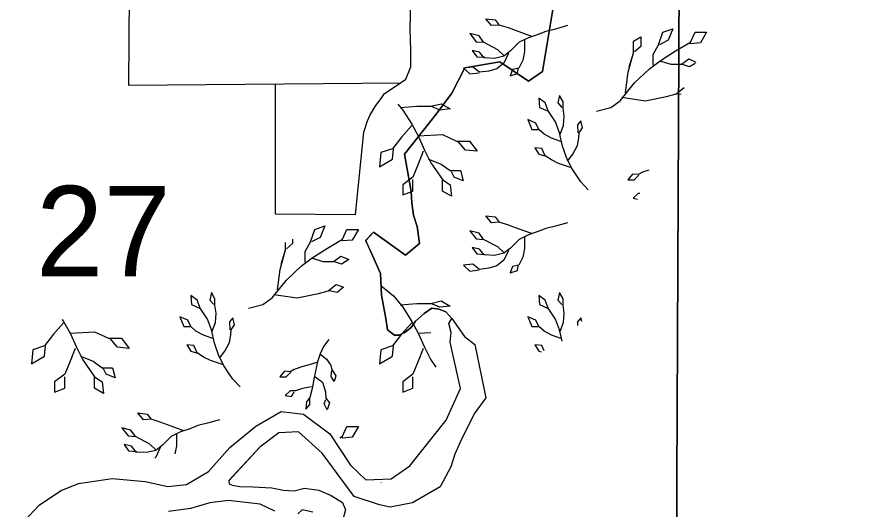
# Model space of a CAD drawing. Extents: x 380424 to 701066, y 1117407 to 1412949.
# Drawn here: x 527994 to 532243, y 1211018 to 1213468 of the extents above; entities that cross this region are included whole.
import ezdxf

# ---------------------------------------------------------------- set-up
doc = ezdxf.new("R2010")
doc.units = 0
for name, color, linetype in [('Local Roads Paved', 7, 'Continuous'), ('Mangroves', 7, 'Continuous'), ('Narrow River Creek and Branch and Slough', 7, 'Continuous'), ('Section Lines', 7, 'Continuous'), ('Section Numbers', 7, 'Continuous'), ('State Park', 7, 'Continuous'), ('Wide Rivers and Canals', 7, 'Continuous')]:
    doc.layers.add(name, color=color, linetype=linetype)

msp = doc.modelspace()

# ---------------------------------------------------------------- linework, layer by layer
at = {"layer": 'Local Roads Paved'}
for points in [[(529276.2, 1213136), (529276.2, 1212490.4), (529676.9, 1212487.4), (529718.1, 1212896.8), (529735.8, 1212952.8), (529747.6, 1212979.3), (529774.1, 1213023.5), (529806.5, 1213067.7), (529821.2, 1213088.4), (529878.2, 1213126.4), (529927.3, 1213159.1), (529950.9, 1213221), (529950.9, 1213303.6), (529947.9, 1213409.7), (529952.2, 1213601.7), (529952.8, 1213787.4), (529961.7, 1216453.7), (528549.8, 1216531.1)], [(528552.5, 1213813.3), (528547.3, 1213129.2), (529901.4, 1213141.9)]]:
    msp.add_lwpolyline(points, dxfattribs=at)
at = {"layer": 'Mangroves'}
for p, q in [((531036.3, 1213220.2), (531058.5, 1213291)), ((529306.3, 1212240.2), (529328.5, 1212311))]:
    msp.add_line(p, q, dxfattribs=at)
for points in [[(530553.3, 1213371.5), (530490.4, 1213394.3), (530436, 1213414.4), (530390.3, 1213428.7), (530353.1, 1213425.8), (530324.5, 1213460.1), (530370.3, 1213454.4), (530390.3, 1213428.7)], [(530730.7, 1213425.8), (530670.6, 1213408.6), (530622, 1213397.2), (530579.1, 1213380), (530536.2, 1213365.7), (530490.4, 1213342.8), (530447.5, 1213299.9), (530413.2, 1213274.2), (530367.4, 1213262.8), (530315.9, 1213265.6), (530293, 1213294.2), (530255.8, 1213302.8), (530278.7, 1213271.3), (530318.8, 1213268.5)], [(530413.2, 1213277.1), (530384.6, 1213305.7), (530313.1, 1213342.8), (530290.2, 1213374.3), (530244.4, 1213385.8), (530275.9, 1213345.7), (530313.1, 1213342.8)], [(531155.8, 1213229), (531155.8, 1213282.2), (531182.4, 1213330.9), (531204.5, 1213392.8), (531253.2, 1213410.5), (531231.1, 1213353), (531186.8, 1213330.9)], [(531341.8, 1213344.1), (531363.9, 1213392.8)], [(531363.9, 1213392.8), (531421.4, 1213392.8)], [(531421.4, 1213392.8), (531390.4, 1213339.7)], [(530516.1, 1213354.3), (530516.1, 1213297.1), (530507.6, 1213254.2), (530487.5, 1213214.1), (530456.1, 1213208.4), (530444.6, 1213176.9), (530481.8, 1213188.4), (530484.7, 1213211.3)], [(531018.6, 1213091.8), (531031.9, 1213193.6), (531058.5, 1213291), (531058.5, 1213348.6), (531093.9, 1213370.7), (531093.9, 1213322), (531062.9, 1213295.4)], [(531266.5, 1213299.9), (531341.8, 1213344.1)], [(531341.8, 1213335.3), (531337.4, 1213339.2)], [(531390.4, 1213339.7), (531341.8, 1213335.3)], [(531191.3, 1213251.2), (531266.5, 1213299.9)], [(530436, 1213288.5), (530413.2, 1213239.9), (530378.8, 1213211.3), (530338.8, 1213199.8), (530293, 1213194.1), (530258.7, 1213219.9), (530212.9, 1213214.1), (530244.4, 1213185.5), (530290.2, 1213191.3)], [(531138.1, 1213211.3), (531191.3, 1213251.2)], [(531186.8, 1213251.2), (531244.4, 1213233.5)], [(531297.5, 1213233.5), (531332.9, 1213260)], [(531332.9, 1213260), (531367.8, 1213244.5)], [(531062.9, 1213140.5), (531138.1, 1213211.3)], [(531244.4, 1213233.5), (531297.5, 1213233.5)], [(531337.3, 1213220.2), (531297.5, 1213233.5)], [(531364.4, 1213237.1), (531337.3, 1213220.2)], [(530992.1, 1213052), (531062.9, 1213140.5)], [(530693.5, 1212886.9), (530710.7, 1212929.8), (530713.5, 1212975.6), (530707.8, 1213015.7), (530707.8, 1213047.1), (530690.6, 1213078.6), (530682, 1213041.4), (530702.1, 1213018.5)], [(531222.2, 1213074.1), (531270.9, 1213087.4)], [(531270.9, 1213087.4), (531310.1, 1213117.8)], [(531294.3, 1213083.2), (531275.4, 1213087.4)], [(529887.5, 1213035.2), (529910.8, 1213005.4)], [(529898, 1213018.2), (529981.1, 1213024.6), (530051.3, 1213024.6), (530102.5, 1213037.3), (530147.2, 1213011.8), (530096.1, 1213005.4), (530051.3, 1213024.6)], [(530833.6, 1212609.5), (530796.8, 1212648.8), (530775.7, 1212678.9), (530750.7, 1212718.2), (530725, 1212769.7), (530704.9, 1212826.9), (530690.6, 1212892.7), (530670.6, 1212947), (530633.4, 1213001.4), (530619.1, 1213041.4), (530587.7, 1213064.3), (530590.5, 1213018.5), (530630.6, 1213001.4)], [(530945.6, 1213018.8), (530992.1, 1213052)], [(531000.9, 1213069.7), (531116, 1213052)], [(531116, 1213052), (531222.2, 1213074.1)], [(529910.8, 1213005.4), (529955.5, 1212935.1)], [(530874.8, 1213001.1), (530945.6, 1213018.8)], [(530696.3, 1212849.8), (530650.6, 1212866.9), (530613.4, 1212886.9), (530587.7, 1212909.8), (530573.4, 1212941.3), (530533.3, 1212958.4), (530553.3, 1212909.8), (530584.8, 1212909.8)], [(530730.5, 1212751.7), (530756.4, 1212786.8), (530779.3, 1212829.7), (530786, 1212868.5), (530787.9, 1212892.7), (530805, 1212918.4), (530796.5, 1212952.7), (530779.3, 1212932.7), (530782.2, 1212892.7)], [(529955.5, 1212928.7), (529904.4, 1212871.2)], [(529955.5, 1212935.1), (529987.4, 1212877.6)], [(529904.4, 1212871.2), (529859.6, 1212813.7)], [(529987.4, 1212877.6), (530108.8, 1212884), (530179.1, 1212852), (530243, 1212852), (530281.4, 1212800.9), (530223.9, 1212807.3), (530185.5, 1212852)], [(529987.4, 1212877.6), (530019.4, 1212807.3)], [(529802.1, 1212794.5), (529795.8, 1212724.2)], [(529859.6, 1212813.7), (529802.1, 1212794.5)], [(529859.6, 1212762.6), (529866, 1212813.7)], [(530013, 1212800.9), (529987.4, 1212737), (529961.9, 1212673.1), (529910.8, 1212634.8), (529910.8, 1212583.7), (529961.9, 1212602.8), (529961.9, 1212660.3)], [(530019.4, 1212807.3), (530051.3, 1212743.4)], [(530745, 1212721), (530710.7, 1212732.5), (530684.9, 1212741.1), (530650.6, 1212758.2), (530619.1, 1212778.2), (530602, 1212815.4), (530567.6, 1212818.3), (530587.7, 1212786.8), (530616.3, 1212778.2)], [(529795.8, 1212724.2), (529859.6, 1212762.6)], [(530038.6, 1212762.6), (530102.5, 1212737), (530147.2, 1212705.1), (530198.3, 1212705.1), (530211.1, 1212654), (530166.4, 1212673.1), (530153.6, 1212698.7)], [(530051.3, 1212743.4), (530108.8, 1212660.3)], [(531102.1, 1212696.4), (531082.1, 1212685)], [(531133.9, 1212707), (531102.1, 1212696.4)], [(530108.8, 1212660.3), (530147.2, 1212634.8)], [(530108.8, 1212602.8), (530108.8, 1212660.3)], [(531053.5, 1212687.8), (531030.6, 1212659.2)], [(531030.6, 1212659.2), (531062.1, 1212659.2)], [(531082.1, 1212685), (531053.5, 1212687.8)], [(531062.1, 1212659.2), (531085, 1212682.1)], [(530147.2, 1212634.8), (530153.6, 1212577.3)], [(530153.6, 1212577.3), (530108.8, 1212602.8)], [(531082.1, 1212590.6), (531056.4, 1212567.7)], [(531056.4, 1212567.7), (531078.5, 1212563.7)], [(531088.9, 1212590.6), (531082.1, 1212590.6)], [(530730.7, 1212445.8), (530670.6, 1212428.6), (530622, 1212417.2), (530579.1, 1212400), (530536.2, 1212385.7), (530490.4, 1212362.9), (530447.5, 1212319.9), (530413.2, 1212294.2), (530367.4, 1212282.8), (530315.9, 1212285.6), (530293, 1212314.2), (530255.8, 1212322.8), (530278.7, 1212291.3), (530318.8, 1212288.5)], [(530553.3, 1212391.5), (530490.4, 1212414.3), (530436, 1212434.4), (530390.3, 1212448.7), (530353.1, 1212445.8), (530324.5, 1212480.1), (530370.3, 1212474.4), (530390.3, 1212448.7)], [(529452.4, 1212350.8), (529474.5, 1212412.8)], [(529474.5, 1212412.8), (529523.2, 1212430.5)], [(529523.2, 1212430.5), (529501.1, 1212373)], [(529611.8, 1212364.1), (529633.9, 1212412.8)], [(529633.9, 1212412.8), (529691.4, 1212412.8)], [(529691.4, 1212412.8), (529660.4, 1212359.7)], [(530413.2, 1212297.1), (530384.6, 1212325.7), (530313.1, 1212362.9), (530290.2, 1212394.3), (530244.4, 1212405.8), (530275.9, 1212365.7), (530313.1, 1212362.9)], [(529363.9, 1212364.9), (529363.9, 1212342)], [(529501.1, 1212373), (529456.8, 1212350.8)], [(529536.5, 1212319.9), (529611.8, 1212364.1)], [(529611.8, 1212355.3), (529607.4, 1212359.2)], [(529660.4, 1212359.7), (529611.8, 1212355.3)], [(530516.1, 1212374.3), (530516.1, 1212317.1), (530507.6, 1212274.2), (530487.5, 1212234.1), (530456.1, 1212228.4), (530444.6, 1212197), (530481.8, 1212208.4), (530484.7, 1212231.3)], [(529328.5, 1212311), (529328.5, 1212348.3)], [(529363.9, 1212342), (529332.9, 1212315.4)], [(529425.8, 1212302.2), (529452.4, 1212350.8)], [(529461.3, 1212271.2), (529536.5, 1212319.9)], [(529301.9, 1212213.6), (529328.5, 1212311)], [(529408.1, 1212231.3), (529461.3, 1212271.2)], [(529425.8, 1212249), (529425.8, 1212302.2)], [(529456.8, 1212271.2), (529514.4, 1212253.5), (529567.5, 1212253.5), (529602.9, 1212280), (529642.7, 1212262.3), (529607.3, 1212240.2), (529567.5, 1212253.5)], [(530436, 1212308.5), (530413.2, 1212259.9), (530378.8, 1212231.3), (530338.8, 1212219.8), (530293, 1212214.1), (530258.7, 1212239.9), (530212.9, 1212234.1), (530244.4, 1212205.5), (530290.2, 1212211.3)], [(529332.9, 1212160.5), (529408.1, 1212231.3)], [(529288.6, 1212111.8), (529301.9, 1212213.6)], [(529262.1, 1212072), (529332.9, 1212160.5)], [(529270.9, 1212089.7), (529386, 1212072), (529492.2, 1212094.1), (529540.9, 1212107.4), (529580.8, 1212138.4), (529616.2, 1212125.1), (529585.2, 1212098.5), (529545.4, 1212107.4)], [(529802.1, 1212134), (529866, 1212082.9), (529910.8, 1212025.4), (529955.5, 1211955.1), (529987.4, 1211897.6), (530019.4, 1211827.3), (530051.3, 1211763.4), (530075.8, 1211728)], [(529103.6, 1211629.5), (529066.8, 1211668.8), (529045.7, 1211698.9), (529020.7, 1211738.2), (528995, 1211789.7), (528974.9, 1211846.9), (528960.6, 1211912.7), (528940.6, 1211967), (528903.4, 1212021.3), (528889.1, 1212061.4), (528857.7, 1212084.3), (528860.5, 1212038.5), (528900.6, 1212021.3)], [(528963.5, 1211906.9), (528980.7, 1211949.8), (528983.5, 1211995.6), (528977.8, 1212035.6), (528977.8, 1212067.1), (528960.6, 1212098.6), (528952.1, 1212061.4), (528972.1, 1212038.5)], [(529215.6, 1212038.8), (529262.1, 1212072)], [(529898, 1212038.2), (529981.1, 1212044.6), (530051.3, 1212044.6), (530102.5, 1212057.3), (530147.2, 1212031.8), (530096.1, 1212025.4), (530051.3, 1212044.6)], [(530619.1, 1212061.4), (530587.7, 1212084.3)], [(530587.7, 1212084.3), (530590.5, 1212038.5)], [(530633.4, 1212021.4), (530619.1, 1212061.4)], [(530693.5, 1211906.9), (530710.7, 1211949.8), (530713.5, 1211995.6), (530707.8, 1212035.7), (530707.8, 1212067.1), (530690.6, 1212098.6), (530682, 1212061.4), (530702.1, 1212038.5)], [(529144.8, 1212021.1), (529215.6, 1212038.8)], [(530590.5, 1212038.5), (530630.6, 1212021.4)], [(530670.6, 1211967), (530633.4, 1212021.4)], [(528966.4, 1211869.7), (528920.6, 1211886.9), (528883.4, 1211906.9), (528857.7, 1211929.8), (528843.4, 1211961.3), (528803.3, 1211978.4), (528823.3, 1211929.8), (528854.8, 1211929.8)], [(529000.5, 1211771.7), (529026.4, 1211806.8), (529049.3, 1211849.7), (529056, 1211888.5), (529057.9, 1211912.7), (529075, 1211938.4), (529066.5, 1211972.7), (529049.3, 1211952.7), (529052.2, 1211912.7)], [(530696.3, 1211869.8), (530650.6, 1211886.9), (530613.4, 1211906.9), (530587.7, 1211929.8), (530573.4, 1211961.3), (530533.3, 1211978.4), (530553.3, 1211929.8), (530584.8, 1211929.8)], [(530796.5, 1211972.7), (530779.3, 1211952.7)], [(530801, 1211954.6), (530796.5, 1211972.7)], [(528225.5, 1211948.7), (528174.4, 1211891.2)], [(528218.2, 1211966.6), (528225.5, 1211955.1)], [(528225.5, 1211955.1), (528257.4, 1211897.6)], [(529955.5, 1211948.7), (529904.4, 1211891.2), (529859.6, 1211833.7), (529802.1, 1211814.5), (529795.8, 1211744.2), (529859.6, 1211782.6), (529866, 1211833.7)], [(530690.6, 1211912.7), (530670.6, 1211967)], [(530779.3, 1211952.7), (530780.6, 1211934.2)], [(528174.4, 1211891.2), (528129.7, 1211833.7)], [(528257.4, 1211897.6), (528378.8, 1211904), (528449.1, 1211872), (528513, 1211872), (528551.4, 1211820.9), (528493.9, 1211827.3), (528455.5, 1211872)], [(528257.4, 1211897.6), (528289.4, 1211827.3)], [(529987.4, 1211897.6), (530050.6, 1211900.9)], [(530702.9, 1211856.4), (530690.6, 1211912.7)], [(529543.8, 1211865.2), (529518, 1211830.8), (529500.9, 1211793.6), (529486.6, 1211753.6), (529478, 1211707.8), (529469.1, 1211668.1), (529460.8, 1211622), (529449.4, 1211576.3), (529432.2, 1211556.2), (529429.4, 1211519.1), (529449.4, 1211541.9), (529449.4, 1211576.3)], [(528072.1, 1211814.5), (528065.8, 1211744.2)], [(528129.7, 1211833.7), (528072.1, 1211814.5)], [(528129.7, 1211782.6), (528136, 1211833.7)], [(528283, 1211820.9), (528257.4, 1211757), (528231.9, 1211693.1), (528180.8, 1211654.8), (528180.8, 1211603.7), (528231.9, 1211622.8), (528231.9, 1211680.3)], [(528289.4, 1211827.3), (528321.3, 1211763.4)], [(529015, 1211741), (528980.7, 1211752.5), (528954.9, 1211761.1), (528920.6, 1211778.2), (528889.1, 1211798.2), (528872, 1211835.4), (528837.6, 1211838.3), (528857.7, 1211806.8), (528886.3, 1211798.2)], [(530013, 1211820.9), (529987.4, 1211757), (529961.9, 1211693.1), (529910.8, 1211654.8), (529910.8, 1211603.7), (529961.9, 1211622.8), (529961.9, 1211680.3)], [(530602, 1211835.4), (530567.6, 1211838.3)], [(530567.6, 1211838.3), (530587.7, 1211806.8)], [(530587.7, 1211806.8), (530599.6, 1211803.2)], [(530614.1, 1211809.1), (530602, 1211835.4)], [(528065.8, 1211744.2), (528129.7, 1211782.6)], [(528308.6, 1211782.6), (528372.5, 1211757), (528417.2, 1211725.1), (528468.3, 1211725.1), (528481.1, 1211673.9), (528436.4, 1211693.1), (528423.6, 1211718.7)], [(528321.3, 1211763.4), (528378.8, 1211680.3)], [(529503.7, 1211790.8), (529532.3, 1211767.9), (529552.3, 1211739.3), (529560.9, 1211713.6), (529578.1, 1211684.9), (529569.5, 1211656.3), (529555.2, 1211682.1), (529558.1, 1211710.7)], [(529483.7, 1211750.7), (529446.5, 1211739.3), (529415.1, 1211730.7), (529372.1, 1211716.4), (529352.1, 1211705), (529323.5, 1211707.8), (529300.6, 1211679.2), (529332.1, 1211679.2), (529355, 1211702.1)], [(528378.8, 1211680.3), (528417.2, 1211654.8)], [(528378.8, 1211622.8), (528378.8, 1211680.3)], [(529475.1, 1211679.2), (529512.3, 1211653.5), (529526.6, 1211604.9), (529529.5, 1211573.4), (529546.6, 1211550.5), (529535.2, 1211516.2), (529520.9, 1211544.8), (529529.5, 1211567.7)], [(528417.2, 1211654.8), (528423.6, 1211597.3)], [(528423.6, 1211597.3), (528378.8, 1211622.8)], [(529458, 1211630.6), (529412.2, 1211622), (529377.9, 1211610.6), (529352.1, 1211610.6), (529326.4, 1211587.7), (529357.8, 1211582), (529372.1, 1211604.9)], [(528823.3, 1211411.4), (528760.4, 1211434.3), (528706, 1211454.4), (528660.3, 1211468.7), (528623.1, 1211465.8), (528594.5, 1211500.1), (528640.3, 1211494.4), (528660.3, 1211468.7)], [(529000.7, 1211465.8), (528940.6, 1211448.6)], [(528683.2, 1211317.1), (528654.6, 1211345.7), (528583.1, 1211382.8), (528560.2, 1211414.3), (528514.4, 1211425.7), (528545.9, 1211385.7), (528583.1, 1211382.8)], [(528849.1, 1211420), (528806.2, 1211405.7)], [(528892, 1211437.2), (528849.1, 1211420)], [(528940.6, 1211448.6), (528892, 1211437.2)], [(529611.8, 1211384.1), (529633.9, 1211432.8)], [(529633.9, 1211432.8), (529691.4, 1211432.8)], [(529691.4, 1211432.8), (529660.4, 1211379.7)], [(528760.4, 1211382.8), (528717.5, 1211339.9)], [(528806.2, 1211405.7), (528760.4, 1211382.8)], [(528786.1, 1211394.3), (528786.1, 1211337.1), (528777.9, 1211296.1)], [(529599.1, 1211376.7), (529611.8, 1211384.1)], [(529611.8, 1211375.3), (529607.4, 1211379.2)], [(529660.4, 1211379.7), (529611.8, 1211375.3)], [(528563, 1211334.2), (528525.8, 1211342.8)], [(528525.8, 1211342.8), (528548.7, 1211311.3)], [(528585.9, 1211305.6), (528563, 1211334.2)], [(528717.5, 1211339.9), (528683.2, 1211314.2)], [(528548.7, 1211311.3), (528588.8, 1211308.5)], [(528637.4, 1211302.8), (528585.9, 1211305.6)], [(528683.2, 1211314.2), (528637.4, 1211302.8)], [(528706, 1211328.5), (528683.2, 1211279.9), (528678.2, 1211275.7)], [(529802.1, 1211154), (529804.2, 1211152.4)]]:
    msp.add_lwpolyline(points, dxfattribs=at)
at = {"layer": 'Narrow River Creek and Branch and Slough'}
msp.add_lwpolyline([(530155.1, 1211969.1), (530125.4, 1212003.6), (530090.8, 1212016.6), (530056.3, 1212020.9), (530017.3, 1211995), (529974.1, 1211956), (529952.5, 1211925.7), (529922.2, 1211899.8), (529891.9, 1211886.8), (529870.3, 1211886.8), (529835.7, 1211912.8), (529827.1, 1211969), (529805.4, 1212085.8), (529801.1, 1212194), (529753.6, 1212297.8), (529727.6, 1212358.2), (529766.4, 1212398.3), (529925.1, 1212285.1), (529993.7, 1212343.1), (529982.7, 1212427.4), (529965.4, 1212483.7), (529956.8, 1212544.2), (529952.5, 1212601.7), (529920.2, 1212787.4), (530076.5, 1212985.6), (530155.7, 1213089.4), (530219.5, 1213216.5), (530393.5, 1213245.2), (530536.2, 1213150), (530605.4, 1213197.6), (530657.1, 1213506.5)], dxfattribs=at)
at = {"layer": 'Section Lines'}
for points in [[(531291.5, 1215071.4), (531267.3, 1209738.6), (525952.8, 1209817.2), (525935.5, 1209817.3), (525956.8, 1210996.7), (525950.4, 1215167.4), (525950.5, 1215199.4), (525970.3, 1215199.3)], [(536654.5, 1214912.8), (536654.3, 1214903.1), (536609.2, 1212169.2), (536591.7, 1209670.3), (531267.3, 1209738.6), (531291.5, 1215071.4)]]:
    msp.add_lwpolyline(points, close=True, dxfattribs=at)
at = {"layer": 'State Park'}
for points in [[(530657.1, 1213506.5), (530605.4, 1213197.6), (530536.2, 1213150), (530393.5, 1213245.2), (530219.5, 1213216.5), (530155.7, 1213089.4), (530076.5, 1212985.6), (529920.2, 1212787.4), (529952.5, 1212601.7), (529956.8, 1212544.2), (529965.4, 1212483.7), (529982.7, 1212427.4), (529993.7, 1212343.1), (529925.1, 1212285.1), (529766.4, 1212398.3), (529726.3, 1212356.9), (529753.6, 1212297.8), (529801.1, 1212194), (529805.4, 1212085.8), (529827.1, 1211969), (529835.7, 1211912.8), (529870.3, 1211886.8), (529891.9, 1211886.8), (529922.2, 1211899.8), (529952.5, 1211925.7), (529974.1, 1211956), (530017.3, 1211995), (530056.3, 1212020.9), (530090.8, 1212016.6), (530125.4, 1212003.6), (530155.1, 1211969.1), (530218.4, 1211881), (530269, 1211840), (530323.4, 1211575), (530265.4, 1211496), (530197.4, 1211359), (530170.4, 1211296), (530149.4, 1211233), (530096.4, 1211132), (529959.4, 1211053), (529849.4, 1211032), (529796.4, 1211043), (529669.4, 1211085), (529511.4, 1211299.5), (529392.5, 1211405.5), (529295.2, 1211401.2), (529200.1, 1211329.8), (529046.2, 1211163.2), (529048.7, 1211148.1), (529063.8, 1211141.6), (529100.6, 1211135.1), (529165.5, 1211132.9), (529260.6, 1211128.6), (529319, 1211115.6), (529370.9, 1211113.5), (529422.8, 1211126.4), (529494.1, 1211115.6), (529554.6, 1211089.7), (529610.9, 1211055), (529626, 1211018.3), (529615.2, 1210977.2)], [(529275.7, 1211011.8), (529202.2, 1211046.4), (529045.3, 1211064.1), (528952.4, 1211053), (528856.3, 1211024.8), (528746.4, 1211011)], [(529463.8, 1211007.4), (529411.9, 1211018.3), (529390.3, 1210998.8)]]:
    msp.add_lwpolyline(points, dxfattribs=at)
at = {"layer": 'Wide Rivers and Canals'}
for points in [[(528027, 1210960.7), (528105, 1211044.1), (528212.6, 1211114.1), (528298.7, 1211149.1), (528467.1, 1211174), (528631.4, 1211158.9), (528743.8, 1211135.1), (528836.8, 1211143.7), (528944.9, 1211208.6), (529052.4, 1211328), (529180.6, 1211433.6), (529306, 1211507.2), (529418.4, 1211494.2), (529548.2, 1211396.8), (529651.9, 1211241.1), (529727.6, 1211167.5), (529853, 1211171.9), (529946, 1211236.8), (530127.6, 1211463.9), (530199, 1211621.8), (530147.1, 1211852.2), (530151.4, 1211899.8), (530140, 1211944.9), (530155.1, 1211969.1), (530218.4, 1211881), (530269, 1211840), (530323.4, 1211575), (530265.4, 1211496), (530197.4, 1211359), (530170.4, 1211296), (530149.4, 1211233), (530096.4, 1211132), (529959.4, 1211053), (529849.4, 1211032), (529796.4, 1211043), (529669.4, 1211085), (529511.4, 1211299.5), (529392.5, 1211405.5), (529295.2, 1211401.2), (529200.1, 1211329.8), (529047.2, 1211164.3), (529048.7, 1211148.1), (529063.8, 1211141.6), (529100.6, 1211135.1), (529165.5, 1211132.9), (529260.6, 1211128.6), (529319, 1211115.6), (529370.9, 1211113.5), (529422.8, 1211126.4), (529494.1, 1211115.6), (529554.6, 1211089.7), (529610.9, 1211055), (529626, 1211018.3), (529615.2, 1210977.2)], [(529275.7, 1211011.8), (529202.2, 1211046.4), (529045.7, 1211064.1), (528952.4, 1211053), (528856.3, 1211024.8), (528746.4, 1211011)], [(529463.8, 1211007.4), (529411.9, 1211018.3), (529390.3, 1210998.8)]]:
    msp.add_lwpolyline(points, dxfattribs=at)

# ---------------------------------------------------------------- texts
at = {"layer": 'Section Numbers'}
msp.add_text('27', height=450, rotation=0.0003, dxfattribs=at).set_placement((528088.2, 1212178.8))

doc.saveas('drawing.dxf')
